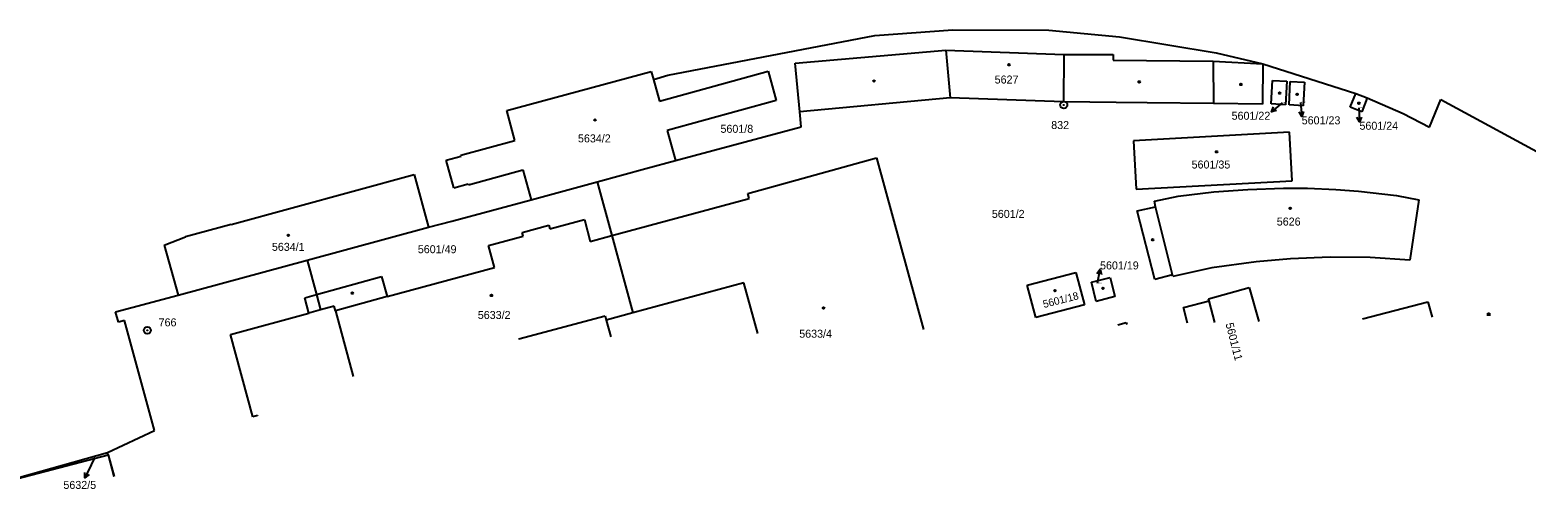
# Model space of a CAD drawing. Extents: x -825057 to -819383, y -1071633 to -1067888.
# Drawn here: x -821360.1 to -821042.1, y -1070249.3 to -1070151.6 of the extents above; entities that cross this region are included whole.
import ezdxf

# ---------------------------------------------------------------- set-up
doc = ezdxf.new("R2010")
doc.units = 0
for name, color, linetype in [('Vrstva 1', 7, 'Continuous'), ('Vrstva 16', 7, 'Continuous'), ('Vrstva 17', 7, 'Continuous'), ('Vrstva 18', 7, 'Continuous'), ('Vrstva 19', 7, 'Continuous'), ('Vrstva 24', 7, 'Continuous'), ('Vrstva 25', 7, 'Continuous'), ('Vrstva 4', 7, 'Continuous')]:
    doc.layers.add(name, color=color, linetype=linetype)

msp = doc.modelspace()

# ---------------------------------------------------------------- linework, layer by layer
at = {"layer": 'Vrstva 1'}
for p, q in [((-821224.5, -1070161.24), (-821180.55, -1070152.81)), ((-821180.55, -1070152.81), (-821163.95, -1070151.61)), ((-821163.95, -1070151.61), (-821143.55, -1070151.69)), ((-821143.55, -1070151.69), (-821128.56, -1070153.06)), ((-821128.56, -1070153.06), (-821108, -1070156.52)), ((-821197.43, -1070158.72), (-821165.45, -1070155.95)), ((-821165.45, -1070155.95), (-821140.36, -1070156.81)), ((-821140.36, -1070156.81), (-821129.86, -1070156.83)), ((-821129.86, -1070156.83), (-821129.85, -1070158.03)), ((-821108, -1070156.52), (-821098.1, -1070158.83)), ((-821258.73, -1070168.78), (-821228.07, -1070160.45)), ((-821228.07, -1070160.45), (-821227.59, -1070162.16)), ((-821226.3, -1070166.8), (-821203.21, -1070160.37)), ((-821203.21, -1070160.37), (-821201.48, -1070166.64)), ((-821196.49, -1070169.04), (-821197.43, -1070158.72)), ((-821129.85, -1070158.03), (-821108.61, -1070158.27)), ((-821108.61, -1070158.27), (-821098.1, -1070158.83)), ((-821098.1, -1070158.83), (-821098.15, -1070167.39)), ((-821098.1, -1070158.83), (-821078.33, -1070165.11)), ((-821227.59, -1070162.16), (-821224.5, -1070161.24)), ((-821227.59, -1070162.16), (-821226.3, -1070166.8)), ((-821096.3, -1070167.37), (-821096.03, -1070162.37)), ((-821096.03, -1070162.37), (-821093, -1070162.53)), ((-821093, -1070162.53), (-821093.26, -1070167.53)), ((-821092.52, -1070167.57), (-821092.25, -1070162.57)), ((-821092.25, -1070162.57), (-821089.24, -1070162.74)), ((-821089.24, -1070162.74), (-821089.51, -1070167.73)), ((-821201.48, -1070166.64), (-821224.62, -1070173.04)), ((-821164.54, -1070166.03), (-821196.49, -1070169.04)), ((-821140.43, -1070166.93), (-821164.54, -1070166.03)), ((-821129.26, -1070167.05), (-821140.43, -1070166.93)), ((-821122.63, -1070167.12), (-821129.26, -1070167.05)), ((-821108.55, -1070167.27), (-821122.63, -1070167.12)), ((-821098.15, -1070167.39), (-821108.55, -1070167.27)), ((-821093.26, -1070167.53), (-821096.3, -1070167.37)), ((-821079.53, -1070168.08), (-821078.33, -1070165.11)), ((-821078.33, -1070165.11), (-821075.91, -1070166.06)), ((-821075.91, -1070166.06), (-821077.08, -1070169.04)), ((-821075.91, -1070166.06), (-821068.26, -1070169.37)), ((-821062.65, -1070172.3), (-821060.28, -1070166.43)), ((-821060.28, -1070166.43), (-821035.7, -1070179.73)), ((-821256.99, -1070175.14), (-821258.73, -1070168.78)), ((-821196.21, -1070172.24), (-821196.49, -1070169.04)), ((-821089.51, -1070167.73), (-821092.52, -1070167.57)), ((-821077.08, -1070169.04), (-821079.53, -1070168.08)), ((-821068.26, -1070169.37), (-821062.65, -1070172.3)), ((-821224.62, -1070173.04), (-821222.86, -1070179.41)), ((-821222.86, -1070179.41), (-821196.21, -1070172.24)), ((-821092.38, -1070173.39), (-821125.56, -1070175.19)), ((-821091.82, -1070183.72), (-821092.38, -1070173.39)), ((-821268.5, -1070178.28), (-821256.99, -1070175.14)), ((-821125.56, -1070175.19), (-821125, -1070185.51)), ((-821271.61, -1070179.35), (-821268.45, -1070178.46)), ((-821269.97, -1070185.21), (-821271.61, -1070179.35)), ((-821268.45, -1070178.46), (-821268.5, -1070178.28)), ((-821229.18, -1070181.11), (-821222.86, -1070179.41)), ((-821207.52, -1070186.43), (-821180.15, -1070178.8)), ((-821180.15, -1070178.8), (-821170.17, -1070215.33)), ((-821317.32, -1070193.01), (-821278.41, -1070182.38)), ((-821278.41, -1070182.38), (-821275.34, -1070193.58)), ((-821266.85, -1070184.55), (-821255.3, -1070181.38)), ((-821255.3, -1070181.38), (-821253.55, -1070187.73)), ((-821239.54, -1070183.92), (-821229.18, -1070181.11)), ((-821269.97, -1070185.21), (-821266.9, -1070184.38)), ((-821266.9, -1070184.38), (-821266.85, -1070184.55)), ((-821253.55, -1070187.73), (-821239.54, -1070183.92)), ((-821239.54, -1070183.92), (-821236.44, -1070195.36)), ((-821207.22, -1070187.44), (-821207.52, -1070186.43)), ((-821125, -1070185.51), (-821091.82, -1070183.72)), ((-821116.04, -1070186.99), (-821108.46, -1070186.03)), ((-821108.46, -1070186.03), (-821101.3, -1070185.59)), ((-821101.3, -1070185.59), (-821093.71, -1070185.3)), ((-821093.71, -1070185.3), (-821088.62, -1070185.31)), ((-821088.62, -1070185.31), (-821082.59, -1070185.59)), ((-821082.59, -1070185.59), (-821077.75, -1070185.93)), ((-821077.75, -1070185.93), (-821069.67, -1070186.87)), ((-821270.42, -1070192.32), (-821253.55, -1070187.73)), ((-821236.44, -1070195.36), (-821207.22, -1070187.44)), ((-821124.79, -1070190.12), (-821120.9, -1070189.23)), ((-821121.13, -1070188.01), (-821116.04, -1070186.99)), ((-821120.9, -1070189.23), (-821121.13, -1070188.01)), ((-821069.67, -1070186.87), (-821064.94, -1070187.75)), ((-821064.94, -1070187.75), (-821066.84, -1070200.6)), ((-821275.34, -1070193.58), (-821270.42, -1070192.32)), ((-821249.59, -1070193.94), (-821242.23, -1070191.95)), ((-821242.23, -1070191.95), (-821241, -1070196.6)), ((-821121.06, -1070204.68), (-821124.79, -1070190.12)), ((-821331.51, -1070197.37), (-821326.97, -1070195.65)), ((-821317.32, -1070193.01), (-821326.97, -1070195.65)), ((-821301.17, -1070200.6), (-821275.34, -1070193.58)), ((-821262.63, -1070197.48), (-821255.24, -1070195.48)), ((-821255.45, -1070194.69), (-821249.8, -1070193.16)), ((-821255.24, -1070195.48), (-821255.45, -1070194.69)), ((-821249.8, -1070193.16), (-821249.59, -1070193.94)), ((-821241, -1070196.6), (-821236.44, -1070195.36)), ((-821236.44, -1070195.36), (-821231.96, -1070211.82)), ((-821331.51, -1070197.37), (-821328.58, -1070208.04)), ((-821261.36, -1070202.14), (-821262.63, -1070197.48)), ((-821328.58, -1070208.04), (-821301.17, -1070200.6)), ((-821301.17, -1070200.6), (-821299.19, -1070207.92)), ((-821284.16, -1070208.35), (-821261.36, -1070202.14)), ((-821108.94, -1070202.24), (-821117.19, -1070204.07)), ((-821099.48, -1070200.93), (-821108.94, -1070202.24)), ((-821092.23, -1070200.31), (-821099.48, -1070200.93)), ((-821083.75, -1070199.95), (-821092.23, -1070200.31)), ((-821075.25, -1070200.05), (-821083.75, -1070199.95)), ((-821066.84, -1070200.6), (-821075.25, -1070200.05)), ((-821299.19, -1070207.92), (-821285.33, -1070204.09)), ((-821285.33, -1070204.09), (-821284.16, -1070208.35)), ((-821208.34, -1070205.39), (-821231.96, -1070211.82)), ((-821205.38, -1070216.18), (-821208.34, -1070205.39)), ((-821148.17, -1070205.88), (-821137.83, -1070203.21)), ((-821137.83, -1070203.21), (-821136, -1070210.06)), ((-821134.49, -1070205.28), (-821130.54, -1070204.29)), ((-821133.46, -1070209.39), (-821134.49, -1070205.28)), ((-821130.54, -1070204.29), (-821129.52, -1070208.34)), ((-821117.27, -1070203.71), (-821121.06, -1070204.68)), ((-821117.19, -1070204.07), (-821117.27, -1070203.71)), ((-821338.41, -1070210.69), (-821328.58, -1070208.04)), ((-821301.65, -1070208.6), (-821299.19, -1070207.92)), ((-821300.77, -1070211.83), (-821301.65, -1070208.6)), ((-821299.19, -1070207.92), (-821298.32, -1070211.17)), ((-821146.32, -1070212.82), (-821148.17, -1070205.88)), ((-821129.52, -1070208.34), (-821133.46, -1070209.39)), ((-821109.6, -1070208.83), (-821100.98, -1070206.42)), ((-821100.98, -1070206.42), (-821098.92, -1070213.63)), ((-821341.85, -1070211.6), (-821338.41, -1070210.69)), ((-821341.24, -1070213.79), (-821341.85, -1070211.6)), ((-821317.41, -1070216.39), (-821300.77, -1070211.83)), ((-821295.4, -1070210.38), (-821298.32, -1070211.17)), ((-821295.13, -1070211.36), (-821295.4, -1070210.38)), ((-821295.13, -1070211.36), (-821291.39, -1070225.31)), ((-821231.96, -1070211.82), (-821237.59, -1070213.35)), ((-821136, -1070210.06), (-821146.32, -1070212.82)), ((-821114.95, -1070210.69), (-821109.49, -1070209.25)), ((-821114.08, -1070213.99), (-821114.95, -1070210.69)), ((-821109.49, -1070209.25), (-821109.6, -1070208.83)), ((-821076.9, -1070213.1), (-821063, -1070209.44)), ((-821063, -1070209.44), (-821062.13, -1070212.75)), ((-821050.26, -1070211.89), (-821049.93, -1070211.9)), ((-821050.26, -1070212.46), (-821050.26, -1070211.89)), ((-821049.93, -1070211.9), (-821049.94, -1070212.45)), ((-821339.94, -1070213.45), (-821341.24, -1070213.79)), ((-821333.58, -1070236.8), (-821339.94, -1070213.45)), ((-821256.15, -1070217.29), (-821237.84, -1070212.4)), ((-821237.84, -1070212.4), (-821237.59, -1070213.35)), ((-821237.59, -1070213.35), (-821236.59, -1070216.93)), ((-821128.88, -1070214.34), (-821127.11, -1070213.87)), ((-821127.11, -1070213.87), (-821126.99, -1070214.3)), ((-821312.66, -1070233.89), (-821317.41, -1070216.39)), ((-821256.12, -1070217.39), (-821256.15, -1070217.29)), ((-821311.67, -1070233.62), (-821312.66, -1070233.89)), ((-821311.62, -1070233.8), (-821311.67, -1070233.62)), ((-821343.59, -1070241.49), (-821333.58, -1070236.8)), ((-821371.34, -1070249.29), (-821343.59, -1070241.49)), ((-821368.76, -1070248.62), (-821343.45, -1070241.99)), ((-821343.45, -1070241.99), (-821343.59, -1070241.49)), ((-821343.45, -1070241.99), (-821342.19, -1070246.64)), ((-821343.45, -1070241.99), (-821342.13, -1070246.61))]:
    msp.add_line(p, q, dxfattribs=at)
at = {"layer": 'Vrstva 16'}
for p, q in [((-821093.99, -1070167.13), (-821096.245, -1070169.016)), ((-821090.06, -1070167.07), (-821089.82, -1070170)), ((-821077.7, -1070168.19), (-821077.55, -1070171.156)), ((-821133.22, -1070205.49), (-821132.667, -1070202.541)), ((-821346.29, -1070242.49), (-821347.07, -1070244.16)), ((-821347.07, -1070244.16), (-821348.353, -1070246.872))]:
    msp.add_line(p, q, dxfattribs=at)
for points in [[(-821095.179, -1070168.763), (-821096.245, -1070169.016), (-821095.808, -1070168.011)], [(-821089.412, -1070168.983), (-821089.82, -1070170), (-821090.388, -1070169.063)], [(-821077.105, -1070170.142), (-821077.55, -1070171.156), (-821078.094, -1070170.193)], [(-821133.342, -1070203.432), (-821132.667, -1070202.541), (-821132.36, -1070203.617)], [(-821347.473, -1070246.182), (-821348.353, -1070246.872), (-821348.377, -1070245.754)]]:
    msp.add_lwpolyline(points, dxfattribs=at)
at = {"layer": 'Vrstva 24'}
for centre, radius in [((-821140.38, -1070167.57), 0.75), ((-821140.38, -1070167.57), 0.0327), ((-821335.11, -1070215.51), 0.75), ((-821335.11, -1070215.51), 0.0327)]:
    msp.add_circle(centre, radius, dxfattribs=at)
at = {"layer": 'Vrstva 25'}
for centre in [(-821152.03, -1070159.04), (-821180.7, -1070162.49), (-821124.35, -1070162.67), (-821102.75, -1070163.22), (-821094.51, -1070165.06), (-821090.79, -1070165.3), (-821077.68, -1070167.2), (-821239.98, -1070170.77), (-821107.91, -1070177.55), (-821092.27, -1070189.57), (-821305.15, -1070195.32), (-821121.48, -1070196.26), (-821291.56, -1070207.6), (-821261.98, -1070208.1), (-821142.25, -1070207.08), (-821132.06, -1070206.59), (-821191.43, -1070210.77)]:
    msp.add_circle(centre, 0.175, dxfattribs=at)
at = {"layer": 'Vrstva 4'}
for p, q in [((-821165.45, -1070155.95), (-821164.54, -1070166.03)), ((-821140.36, -1070156.81), (-821140.43, -1070166.93)), ((-821108.61, -1070158.27), (-821108.55, -1070167.27)), ((-821117.27, -1070203.71), (-821120.9, -1070189.23)), ((-821284.16, -1070208.35), (-821295.13, -1070211.36)), ((-821298.32, -1070211.17), (-821300.77, -1070211.83)), ((-821108.28, -1070213.85), (-821109.49, -1070209.25))]:
    msp.add_line(p, q, dxfattribs=at)

# ---------------------------------------------------------------- texts
at = {"layer": 'Vrstva 16'}
for s, p in [('5601/22', (-821104.717, -1070170.72)), ('5601/23', (-821089.82, -1070171.7)), ('5601/24', (-821077.55, -1070172.85)), ('5601/19', (-821132.67, -1070202.56)), ('5632/5', (-821352.942, -1070249.25))]:
    msp.add_text(s, height=1.7, dxfattribs=at).set_placement(p)
at = {"layer": 'Vrstva 17'}
for s, p in [('832', (-821143.045, -1070172.7)), ('766', (-821332.71, -1070214.67))]:
    msp.add_text(s, height=1.7, dxfattribs=at).set_placement(p)
at = {"layer": 'Vrstva 18'}
for s, height, p in [('5601/8', 1.7, (-821213.323, -1070173.5)), ('5601/2', 1.7, (-821155.66, -1070191.6)), ('5601/49', 1.7, (-821277.634, -1070199.11)), ('5632/5', 0.1, (-821346.47, -1070242.49))]:
    msp.add_text(s, height=height, dxfattribs=at).set_placement(p)
at = {"layer": 'Vrstva 19'}
for s, height, p in [('5627', 1.7, (-821155.063, -1070163.02)), ('5601/22', 0.2, (-821093.99, -1070167.13)), ('5601/23', 0.2, (-821090.06, -1070167.07)), ('5601/24', 0.2, (-821077.7, -1070168.19)), ('5634/2', 1.7, (-821243.6, -1070175.54)), ('5601/35', 1.7, (-821113.212, -1070181.1)), ('5626', 1.7, (-821095.118, -1070193.23)), ('5634/1', 1.7, (-821308.638, -1070198.61)), ('5601/19', 0.2, (-821133.22, -1070205.49)), ('5633/2', 1.7, (-821264.887, -1070213.1)), ('5633/4', 1.7, (-821196.592, -1070217.09))]:
    msp.add_text(s, height=height, dxfattribs=at).set_placement(p)
for s, height, rotation, p in [('5601/18', 1.6, 14.4, (-821144.576, -1070210.78)), ('5601/11', 1.7, 284.4, (-821106.023, -1070214.137))]:
    msp.add_text(s, height=height, rotation=rotation, dxfattribs=at).set_placement(p)

doc.saveas('drawing.dxf')
